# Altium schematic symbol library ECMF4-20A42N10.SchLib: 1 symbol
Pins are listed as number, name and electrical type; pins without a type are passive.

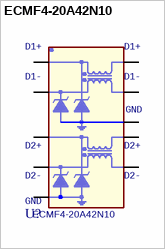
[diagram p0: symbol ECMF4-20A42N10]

## ECMF4-20A42N10
designator U?
footprint ST_QFN40P220X135X50-10L (Footprint not found)
pins: 1 D1+, 2 D1-, 3 GND, 4 D2+, 5 D2-, 6 D2-1, 7 D2+1, 8 GND1, 9 D1-1, 10 D1+1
